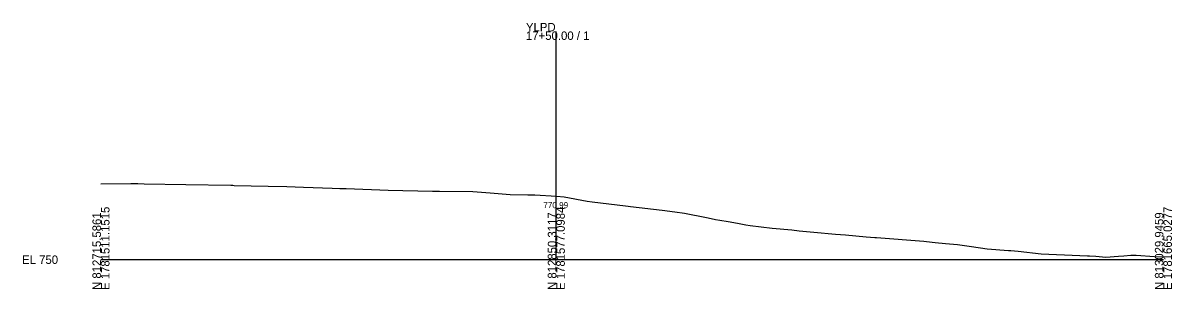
# Model space of a CAD drawing. Extents: x -26 to 353, y -10 to 9080.
# Drawn here: x -25.7 to 352.8, y 7490.3 to 7578.1 of the extents above; entities that cross this region are included whole.
import ezdxf

# ---------------------------------------------------------------- set-up
doc = ezdxf.new("R2010")
doc.units = 0
for name, color, linetype in [('Exist Cross Section Cell', 7, 'Continuous'), ('Exist XS Center Line Elevation Label', 7, 'Continuous'), ('Exist XS Ground Line', 7, 'Continuous')]:
    doc.layers.add(name, color=color, linetype=linetype)

msp = doc.modelspace()

# ---------------------------------------------------------------- linework, layer by layer
at = {"layer": 'Exist Cross Section Cell'}
for p, q in [((150, 7500), (150, 7575.29)), ((0, 7500), (150, 7500)), ((150, 7500), (350, 7500))]:
    msp.add_line(p, q, dxfattribs=at)
at = {"layer": 'Exist XS Ground Line'}
for p, q in [((0, 7525.05), (9.8, 7525.1)), ((9.8, 7525.1), (12.19, 7525.08)), ((12.19, 7525.08), (14.24, 7525.05)), ((14.24, 7525.05), (28.01, 7524.81)), ((28.01, 7524.81), (42.79, 7524.55)), ((42.79, 7524.55), (43.45, 7524.53)), ((43.45, 7524.53), (43.86, 7524.52)), ((43.86, 7524.52), (55.1, 7524.28)), ((55.1, 7524.28), (61.21, 7524.09)), ((61.21, 7524.09), (66.7, 7523.88)), ((66.7, 7523.88), (76.2, 7523.57)), ((76.2, 7523.57), (78.65, 7523.52)), ((78.65, 7523.52), (80.8, 7523.43)), ((80.8, 7523.43), (94.6, 7522.98)), ((94.6, 7522.98), (109.17, 7522.65)), ((109.17, 7522.65), (111.53, 7522.62)), ((111.53, 7522.62), (122.46, 7522.5)), ((122.46, 7522.5), (128.26, 7522.05)), ((128.26, 7522.05), (134.77, 7521.49)), ((134.77, 7521.49), (140.63, 7521.38)), ((140.63, 7521.38), (142.88, 7521.34)), ((142.88, 7521.34), (150.04, 7520.99)), ((150.04, 7520.99), (152.55, 7520.71)), ((152.55, 7520.71), (160.14, 7519.28)), ((160.14, 7519.28), (161.86, 7519.05)), ((161.86, 7519.05), (172.75, 7517.75)), ((172.75, 7517.75), (173.73, 7517.63)), ((173.73, 7517.63), (174.45, 7517.54)), ((174.45, 7517.54), (184.87, 7516.34)), ((184.87, 7516.34), (189.09, 7515.77)), ((189.09, 7515.77), (192.2, 7515.39)), ((192.2, 7515.39), (199.51, 7513.9)), ((199.51, 7513.9), (202.05, 7513.35)), ((202.05, 7513.35), (202.47, 7513.29)), ((202.47, 7513.29), (203.89, 7513.07)), ((203.89, 7513.07), (206.57, 7512.62)), ((206.57, 7512.62), (209.65, 7512.07)), ((209.65, 7512.07), (212.45, 7511.51)), ((212.45, 7511.51), (213.88, 7511.24)), ((213.88, 7511.24), (221.08, 7510.41)), ((221.08, 7510.41), (227.56, 7509.81)), ((227.56, 7509.81), (230.01, 7509.56)), ((230.01, 7509.56), (234.82, 7509.11)), ((234.82, 7509.11), (242, 7508.45)), ((242, 7508.45), (245.31, 7508.16)), ((245.31, 7508.16), (252.11, 7507.58)), ((252.11, 7507.58), (254.98, 7507.32)), ((254.98, 7507.32), (255.53, 7507.31)), ((255.53, 7507.31), (271.07, 7506.07)), ((271.07, 7506.07), (271.93, 7505.98)), ((271.93, 7505.98), (274.78, 7505.62)), ((274.78, 7505.62), (278.23, 7505.28)), ((278.23, 7505.28), (282.15, 7505)), ((282.15, 7505), (286.82, 7504.3)), ((286.82, 7504.3), (291.95, 7503.61)), ((291.95, 7503.61), (299.02, 7503.06)), ((299.02, 7503.06), (299.74, 7502.99)), ((299.74, 7502.99), (302.12, 7502.78)), ((302.12, 7502.78), (309.77, 7501.9)), ((309.77, 7501.9), (322.43, 7501.4)), ((322.43, 7501.4), (325.02, 7501.27)), ((325.02, 7501.27), (325.7, 7501.27)), ((325.7, 7501.27), (327.74, 7501.13)), ((327.74, 7501.13), (330.99, 7500.84)), ((330.99, 7500.84), (335.21, 7501.15)), ((335.21, 7501.15), (336.96, 7501.31)), ((336.96, 7501.31), (339.26, 7501.43)), ((339.26, 7501.43), (340.13, 7501.45)), ((340.13, 7501.45), (340.61, 7501.47)), ((340.61, 7501.47), (341.04, 7501.43)), ((341.04, 7501.43), (347.03, 7500.99)), ((347.03, 7500.99), (350, 7500.9))]:
    msp.add_line(p, q, dxfattribs=at)

# ---------------------------------------------------------------- texts
at = {"layer": 'Exist Cross Section Cell'}
for s, p in [('YLPD', (140, 7575.29)), ('17+50.00 / 1', (140, 7572.49)), ('EL 750', (-26, 7498.6))]:
    msp.add_text(s, height=2.8, dxfattribs=at).set_placement(p)
for s, p in [('N 812715.5861', (0, 7490)), ('E 1781511.1515', (2.8, 7490)), ('N 812850.3117', (150, 7490)), ('E 1781577.0984', (152.8, 7490)), ('N 813029.9459', (350, 7490)), ('E 1781665.0277', (352.8, 7490))]:
    msp.add_text(s, height=2.8, rotation=90, dxfattribs=at).set_placement(p)
at = {"layer": 'Exist XS Center Line Elevation Label'}
msp.add_text('770.99', height=2, dxfattribs=at).set_placement((145.73, 7516.99))

doc.saveas('drawing.dxf')
